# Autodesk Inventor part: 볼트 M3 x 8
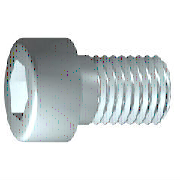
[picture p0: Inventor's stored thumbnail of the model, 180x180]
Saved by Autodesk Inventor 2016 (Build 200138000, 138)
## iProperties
IsCustomPart: 0
Created: 2012-02
Part Number: 볼트 M3 x 8
Material: 스테인리스강
Description: 6각 소켓 머리 캡 나사
Document SubType Name: Modeling
Standard: ISO 4762
Designer: mduedu
Standard Revision: Fourth edition 2004-03-01
Standards Organization: ISO
Language: ko-KR
Size Designation: M3 x 8
Categories: <MemberInstance><Categories><Category DisplayName="조임쇠" InternalName="e4da775c-781d-43d5-af7c-5136215cf5a6" Mnemonic="FSTN"><Category DisplayName="볼트" InternalN
Density: 8.08 g/cm^3
Mass: 0.955869 g
Surface Area: 1.83001 cm^2
Volume: 0.118301 cm^3
Appearance: 반광택
Author: mduedu
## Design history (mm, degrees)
sketch "스케치1"
  geometry: L1 (-0.867, 0)-(8, 0); L2 (8, 0)-(8, 1.5); L3 (8, 1.5)-(1.25, 1.5); L4 (1.25, 1.5)-(0.943, 1.5); L5 (0.943, 1.5)-(0, 1.5); L6 (0, 1.5)-(0, 2.75); L7 (0, 2.75)-(-3, 2.75); L8 (-3, 2.75)-(-3, 1.443); L9 (-3, 1.443)-(-1.7, 1.443); L10 (-1.7, 1.443)-(-0.867, 0); L11 (-5.2, 0)-(10.2, 0) reference; L12 (0, -0.55)-(0, 3.3) reference; L13 (1.25, 1.5)-(0, 1.5)
  constraints: 22 end point, 6 parallel, 2 collinear, 2 perpendicular, 1 horizontal, 1 point on line
  dimensions: "d1" = 6.75 distance from line of L3.end L2 (= GEL); "d2" = 0.30683 distance of L4.end L3.end (computed from GAL); "d3" = 3 distance between parallel lines of L8 L6 (= KOH); "d4" = 1.3 distance of L8.end L9.end (= INTI); "d5" = 60 deg angle of L10 L1; "d6" = 3 diameter of L3 L1 (= GD); "d7" = 3 diameter of L5 L1 (= BDM); "d8" = 2.88675 diameter of L9 L1 (= 1.1547 x SW); "d9" = 5.5 diameter of L7 L1 (= KOD); "d26" = 8 distance between parallel lines of L12 L2 (= NLG)
revolve "본체" sketch "스케치1" stored, may be unused: angle "d10" = 90 deg
sketch "스케치2"
  geometry: L1 (0, -3.85)-(0, 3.85) reference; L2 (-3.85, 0)-(3.85, 0) reference; L3 (1.443, 0)-(0.722, -1.25); L4 (0.722, -1.25)-(-0.722, -1.25); L5 (-0.722, -1.25)-(-1.443, 0); L6 (-1.443, 0)-(-0.722, 1.25); L7 (-0.722, 1.25)-(0.722, 1.25); L8 (0.722, 1.25)-(1.443, 0); 2 further points
  constraints: 12 end point, 1 coincident, 1 horizontal alignment, 1 point on line, 12 other
extrude "슬롯" join sketch "스케치2" stored distance "d11" = 10; taper "d12" = 0 deg
workplane "Work Plane1"
fillet "Fillet2" dims "d30" = 0.1 (= R)
body "Solid1"
fillet "모깎기1" dims "d17" = 0.3 (= RR)
feature "스레드" dims "d13" = 6.75 (= GEL), "d14" = 0
chamfer "모따기1" distance "d15" = 0.30673 (= -0.5 x SPD + 0.5 x GD); stored, may be unused: second distance "d16" = 0.30673 (= GUL), angle "d27" = 45 deg
other parameters: "GD" = 3 [user parameter; used in 2 equation terms], "NLG" = 8 [user parameter; used in 1 equation term], "GEL" = 6.75 [user parameter; used in 2 equation terms], "KOD" = 5.5 [user parameter; used in 1 equation term], "KOH" = 3 [user parameter; used in 1 equation term], "INTI" = 1.3 [user parameter; used in 1 equation term], "GAL" = 0.30673 (= 0.61345 x PTC) [user parameter; used in 1 equation term], "GUL" = 0.30673 (= 0.61345 x PTC) [user parameter; used in 1 equation term], "BDM" = 3 (= NND) [user parameter; used in 1 equation term], "SW" = 2.5 [user parameter; used in 2 equation terms], "RR" = 0.3 [user parameter; used in 1 equation term], "SPD" = 2.38655 (= NND - 1.2269 x PTC) [user parameter; used in 1 equation term], "d19" = 0, "d28" = 0, "d29" = 0, "R" = 0.1 [user parameter; used in 1 equation term], "TOA" = 30 deg [user parameter], "GD1" = 2.38655 (= THREADDIA - 1.2269 x PTC) [user parameter], "THREADDIA" = 3 [user parameter; used in 1 equation term], "FAWI" = 45 deg [user parameter], "PTC" = 0.5 [user parameter; used in 5 equation terms], "NND" = 3 [user parameter; used in 2 equation terms], "E0" = 2.8875 (= 1.155 x SW) [user parameter]
